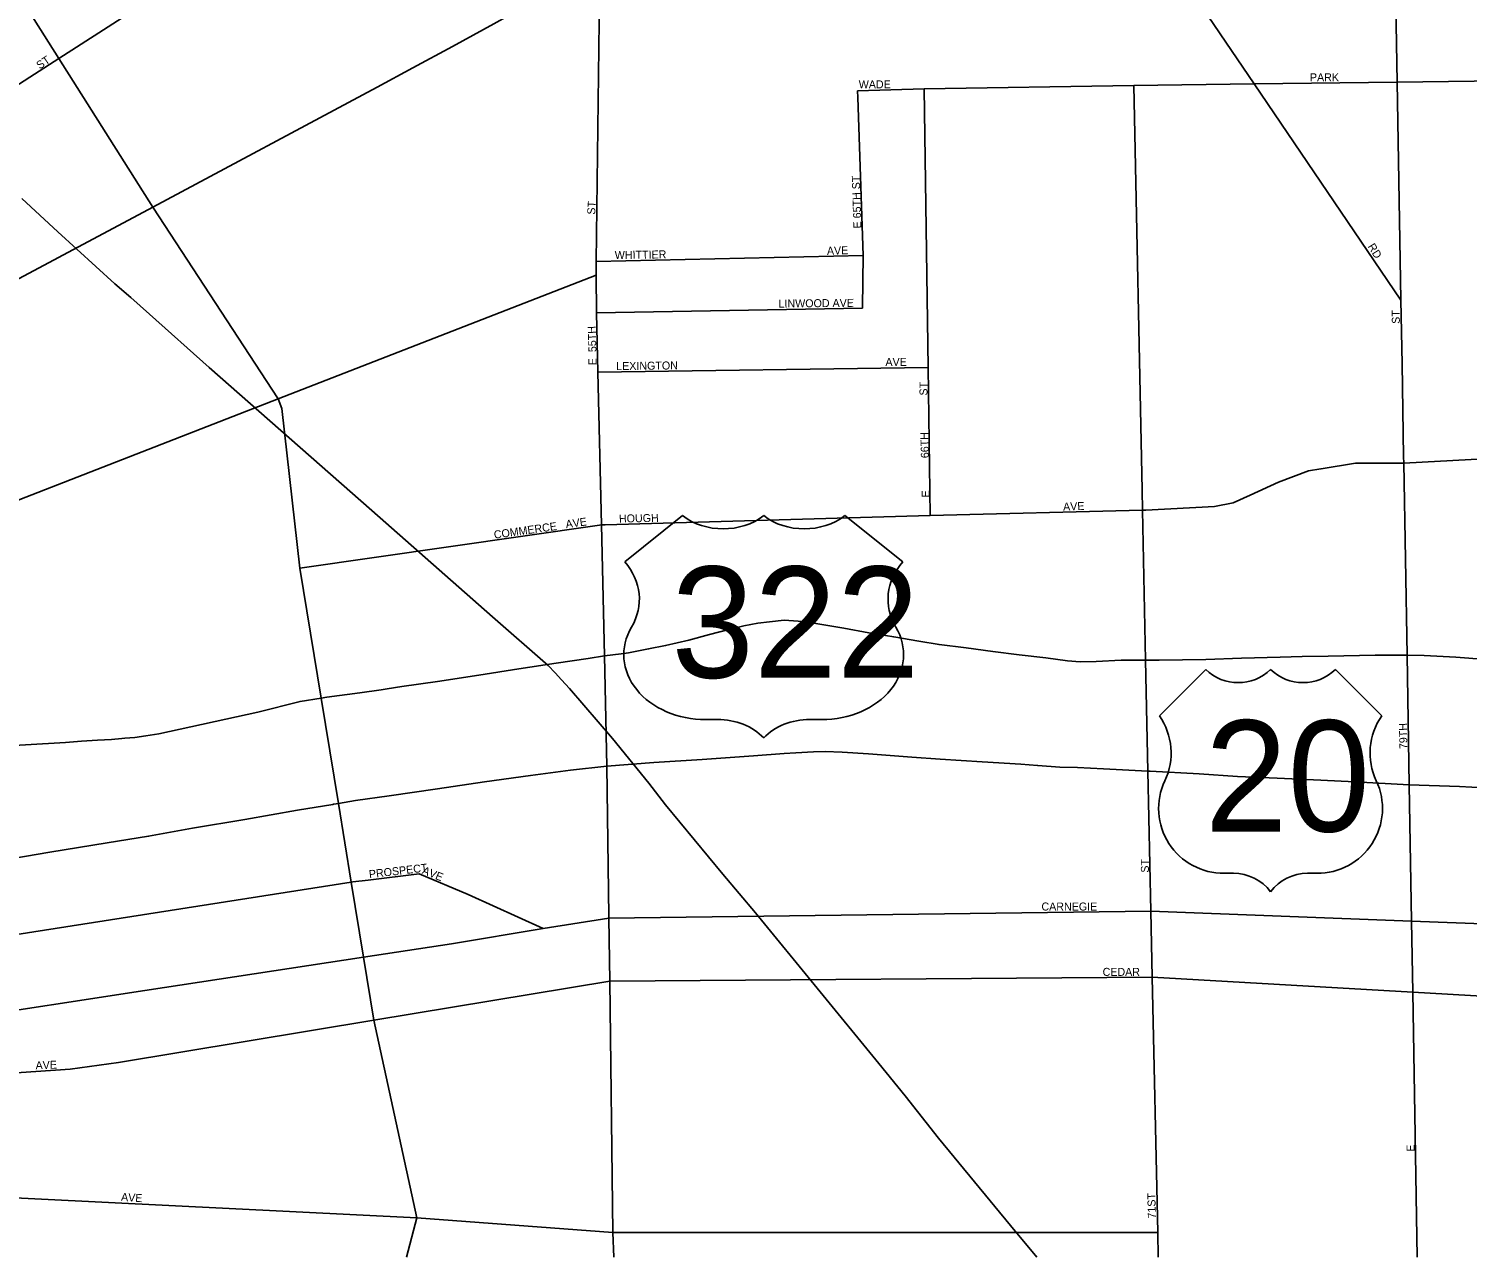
# Model space of a CAD drawing. Extents: x 2139079 to 2262683, y 1235796 to 1334992.
# Drawn here: x 2197328 to 2206334, y 1274636 to 1282328 of the extents above; entities that cross this region are included whole.
import ezdxf

# ---------------------------------------------------------------- set-up
doc = ezdxf.new("R2010")
doc.units = 0
for name, color, linetype in [('GM_X_City_Street', 7, 'Continuous'), ('GM_X_City_Street_Text', 7, 'Continuous'), ('GM_X_Rail_Line', 7, 'Continuous'), ('GM_X_US_Location', 7, 'Continuous'), ('GM_X_US_Route', 7, 'Continuous'), ('GM_X_US_Shield', 7, 'Continuous')]:
    doc.layers.add(name, color=color, linetype=linetype)

msp = doc.modelspace()

# ---------------------------------------------------------------- linework, layer by layer
at = {"layer": 'GM_X_City_Street'}
for points in [[(2205918.6, 1280628.8), (2205000.4, 1281982.7), (2204176.3, 1283197.8), (2202675.4, 1285411)], [(2195567.4, 1280882.4), (2195932.5, 1281121.6), (2196013.9, 1281174.9), (2197516.4, 1282140.7), (2200878.3, 1284302)], [(2199693.1, 1274636.1), (2199757.3, 1274882.4), (2199487.9, 1276121.4), (2199423.7, 1276514.9), (2199347, 1276984.3), (2199266.6, 1277477.3), (2199158.9, 1278137), (2199026, 1278950.7), (2198913.3, 1279950.5), (2198889.4, 1280010.3), (2198105.6, 1281211.1), (2197516.4, 1282140.7), (2197025, 1282915.9), (2196406.7, 1283843.3)], [(2200959.9, 1276772.6), (2200948.1, 1277711.7), (2200932.3, 1278401.1), (2200913.6, 1279220.8), (2200891.7, 1280176.8), (2200883.1, 1280549.8), (2200879.8, 1280784.3), (2200879.9, 1280871.4), (2200904.1, 1282710.1)], [(2205916.4, 1280755.8), (2205895, 1281994.1), (2205884.4, 1282599.7), (2205884.4, 1282599.7)], [(2202934.1, 1281951.1), (2204247.1, 1281973.2), (2205000.4, 1281982.7), (2205895, 1281994.1), (2209270.3, 1282037)], [(2202517.3, 1281938.9), (2202517.3, 1281938.9), (2202934.1, 1281951.1)], [(2202971.3, 1279279.3), (2202958.4, 1280207.2), (2202934.1, 1281951.1)], [(2204298.8, 1279439), (2204247.1, 1281973.2)], [(2202551.7, 1280907.9), (2202518.7, 1281897.1), (2202517.3, 1281938.9)], [(2200879.9, 1280871.4), (2202551.7, 1280907.9)], [(2202551.7, 1280907.9), (2202547.3, 1280584.6)], [(2192078.6, 1277394.3), (2192139, 1277429.1), (2192255.8, 1277493.6), (2192381.1, 1277540.8), (2193054.4, 1277782.2), (2193377.5, 1277898), (2194000, 1278121.1), (2195091.4, 1278534.1), (2195674.4, 1278761.3), (2196370.6, 1279030.8), (2198889.4, 1280010.3), (2200879.8, 1280784.3)], [(2205925.6, 1280228.9), (2205918.6, 1280628.8), (2205916.4, 1280755.8), (2205916.4, 1280755.8)], [(2202547.3, 1280584.6), (2202547.3, 1280584), (2202547.2, 1280578.6), (2200883.1, 1280549.8)], [(2200891.7, 1280176.8), (2202958.4, 1280207.2)], [(2205419.6, 1279573.1), (2205635, 1279607.5), (2205936.3, 1279607.8), (2207201.4, 1279677.6), (2207637.1, 1279689.3), (2207884.5, 1279701), (2208084.7, 1279759.8), (2208237.8, 1279806.9), (2208782.5, 1279945.6), (2209521.7, 1280141), (2209712.5, 1280189.9), (2209796.2, 1280201.6), (2209859.5, 1280204.6), (2209902.3, 1280201.9)], [(2205935.6, 1279649.4), (2205925.6, 1280228.9), (2205925.6, 1280228.9)], [(2206021.4, 1274636.1), (2205993.3, 1276295), (2205985.7, 1276739.7), (2205971.3, 1277594.8), (2205957.2, 1278406.4), (2205936.3, 1279607.8), (2205935.6, 1279649.4), (2205935.6, 1279649.4)], [(2204321.6, 1279314.5), (2204751.7, 1279336.9), (2204869.4, 1279360.5), (2204975.5, 1279407.5), (2205152.1, 1279489.9), (2205340.6, 1279560.5), (2205418.1, 1279572.8), (2205419.6, 1279573.1)], [(2204399.4, 1274636.1), (2204396, 1274790.1), (2204362.3, 1276390.1), (2204353.6, 1276802.7), (2204335.2, 1277679.2), (2204320.5, 1278374.7), (2204301.4, 1279313.5), (2204298.8, 1279439), (2204298.8, 1279439)], [(2200935.9, 1279221.4), (2202971.3, 1279279.3)], [(2202971.3, 1279279.3), (2204301.4, 1279313.5), (2204321.6, 1279314.5)], [(2199026, 1278950.7), (2200900.6, 1279220.4), (2200913.6, 1279220.8), (2200927.2, 1279221.2), (2200935.9, 1279221.4)], [(2194795.5, 1276268.4), (2194808.5, 1276270.4), (2195620.1, 1276396.8), (2195639.2, 1276399.7), (2195927.7, 1276444.6), (2196115.4, 1276475.2), (2196771, 1276582), (2199347, 1276984.3), (2199357.6, 1276985.9), (2199452, 1276997.4)], [(2199452, 1276997.4), (2199453, 1276997.5), (2199771.3, 1277036.1), (2200078.7, 1276907.4), (2200548.3, 1276694.8)], [(2195316.8, 1275884.2), (2195584.4, 1275925.4), (2195898.5, 1275973.8), (2196857.5, 1276121.5), (2198055.8, 1276306.1), (2199423.7, 1276514.9), (2199975.3, 1276599.1), (2200548.3, 1276694.8), (2200960.1, 1276758.7), (2204353.6, 1276802.7), (2205985.7, 1276739.7), (2208329.5, 1276653.5), (2208438.4, 1276656.1), (2209594.3, 1276683.5), (2210249.4, 1276698.5), (2211015.8, 1276660.8), (2211607.3, 1276645.7), (2211689.1, 1276641.1), (2211782.7, 1276635.3), (2211800.4, 1276631.3)], [(2200990.2, 1274636.1), (2200984.9, 1274790.2), (2200965.1, 1276364.1), (2200960.1, 1276758.7), (2200959.9, 1276772.6)], [(2195173.4, 1275563.7), (2195259.9, 1275543.1), (2195320.8, 1275531.8), (2195348.8, 1275529.9), (2195377.3, 1275531.8), (2196923.8, 1275769.9), (2197062.7, 1275778.9), (2197588.4, 1275813.1), (2197889.7, 1275856.3), (2199487.9, 1276121.4), (2200965.1, 1276364.1), (2204362.3, 1276390.1), (2205993.3, 1276295), (2208449.7, 1276154.3), (2211022.8, 1276017.2), (2211423.6, 1275997.3), (2211694.1, 1275984), (2211874.7, 1275974.6), (2211880.2, 1275974.3), (2212100, 1275965.1), (2212268.1, 1275954.8), (2212357.1, 1275951.5)], [(2197028.8, 1275019.3), (2197028.8, 1275019.3), (2199757.3, 1274882.4), (2200984.9, 1274790.2), (2203543.2, 1274790.2), (2203543.2, 1274790.2)], [(2203543.2, 1274790.2), (2203809.7, 1274790.2)], [(2203809.7, 1274790.2), (2203809.7, 1274790.2), (2204396, 1274790.1)]]:
    msp.add_lwpolyline(points, dxfattribs=at)
at = {"layer": 'GM_X_Rail_Line'}
msp.add_lwpolyline([(2197285.3, 1281264.1), (2197511.2, 1281056.8), (2197866.9, 1280730.2), (2197966.9, 1280645.2), (2198084, 1280540), (2198456.8, 1280207.4), (2199475.5, 1279311.8), (2200232.4, 1278646.6), (2200579.9, 1278340.1), (2200624.7, 1278295.3), (2200664.2, 1278252.1), (2200714.2, 1278196.9), (2200983.4, 1277883.7), (2201209.3, 1277604), (2201314.5, 1277469.1), (2201673.9, 1277033.6), (2201877.5, 1276793.4), (2202650.1, 1275848.6), (2202815.6, 1275645.8), (2203024.4, 1275381.8), (2203474.1, 1274835.1), (2203638.7, 1274636.1)], dxfattribs=at)
at = {"layer": 'GM_X_US_Route'}
for points in [[(2195310.7, 1279716.9), (2195406.6, 1279771.5), (2195540.9, 1279843.6), (2195772.2, 1279967.9), (2198105.6, 1281211.1), (2199508.9, 1281962.3), (2199732.1, 1282082.7), (2199981.1, 1282217.3), (2200240.2, 1282358.1), (2200816.9, 1282682.5), (2200904.1, 1282710.1)], [(2201037, 1278415), (2201083.2, 1278421.2), (2201209, 1278444.9), (2201314.9, 1278466.2), (2201460.6, 1278500.2), (2201590.3, 1278535.9), (2201710.1, 1278567.5), (2201803.9, 1278588.7), (2201891.8, 1278605.9), (2201965.7, 1278614.9), (2202057.7, 1278624.1), (2202145.9, 1278619.1), (2202256.2, 1278604.5), (2202430.8, 1278574.6), (2202587.3, 1278546.5), (2202743.8, 1278520.4), (2202900.4, 1278494.3), (2203026.8, 1278471.9), (2203197.2, 1278452), (2203363.7, 1278428), (2203528.1, 1278408), (2203694.6, 1278388.1), (2203831, 1278369.8), (2203911.1, 1278364.8), (2204011.2, 1278366), (2204167.3, 1278374), (2204320.5, 1278374.7), (2204405.6, 1278375), (2204697.9, 1278378.7), (2204920, 1278387.6), (2205162.2, 1278392.6), (2205300.3, 1278396.4), (2205462.5, 1278400.4), (2205756.7, 1278406.2), (2205957.2, 1278406.4), (2206065.1, 1278404), (2206263.4, 1278392.5), (2206449.8, 1278378.8)], [(2199572.9, 1278195.1), (2199664.3, 1278208.7), (2199886.2, 1278241.6), (2200146, 1278281), (2200395.7, 1278320.2), (2200629.6, 1278355.3), (2200830.3, 1278385.7), (2200932.3, 1278401.1)], [(2200932.3, 1278401.1), (2201037, 1278415)], [(2197911.4, 1277883.8), (2197930.5, 1277885.6), (2197992.9, 1277890.4), (2198061.7, 1277900), (2198141.8, 1277912.8), (2198762.9, 1278048.9), (2199026.8, 1278116.4), (2199158.9, 1278137), (2199194.7, 1278142.6), (2199400.5, 1278169.3), (2199535, 1278189.4), (2199572.9, 1278195.1)], [(2196216.8, 1277747.9), (2196386.8, 1277773.9), (2196591.7, 1277805.3), (2196875.6, 1277820), (2197559.1, 1277860), (2197658.4, 1277866.4), (2197757.6, 1277874.4), (2197845.6, 1277877.6), (2197911.4, 1277883.8)], [(2199237.4, 1277472.4), (2199266.6, 1277477.3), (2199373.1, 1277495.2), (2199584.9, 1277525.9), (2199886.7, 1277569.9), (2200180.5, 1277613.7), (2200468.3, 1277651.4), (2200720.2, 1277686.7), (2200948.1, 1277711.7), (2201242.2, 1277733.4), (2201544.3, 1277753.3), (2201866.3, 1277775.4), (2202056.5, 1277789.3), (2202057.8, 1277789.4)], [(2202057.8, 1277789.4), (2202130.4, 1277794.8), (2202240.4, 1277800.2), (2202314.5, 1277803.1), (2202420.7, 1277798.5), (2202585, 1277788.5), (2202857.6, 1277767.9), (2203033.9, 1277754.1), (2203296.4, 1277737.3), (2203538.9, 1277722.4), (2203643.7, 1277715.1)], [(2203643.7, 1277715.1), (2203645.2, 1277715), (2203783.4, 1277705.4), (2203893.6, 1277702.8), (2204055.8, 1277694.8), (2204335.2, 1277679.2), (2204348.4, 1277678.5), (2204654.9, 1277662.3), (2204895.4, 1277645.3), (2205143.8, 1277636.4), (2205416.3, 1277623.8), (2205630.7, 1277612.5), (2205971.3, 1277594.8)], [(2205971.3, 1277594.8), (2206285.8, 1277582.7), (2206594.3, 1277566.5), (2206870.8, 1277554), (2207105.2, 1277542.9), (2207417.7, 1277530.8), (2207720.3, 1277516.6), (2208048.8, 1277502.7), (2208328.4, 1277492), (2208419.5, 1277497.5), (2208650.6, 1277511.6), (2209013.3, 1277524.3), (2209295.9, 1277536.5), (2209590.5, 1277548.8), (2209899.1, 1277561.1), (2210251.7, 1277573.8), (2210544.3, 1277588), (2210889, 1277600.7), (2210987.9, 1277605.5), (2210990.1, 1277605.6)], [(2195969.9, 1276936), (2196047.8, 1276947.6), (2196707.8, 1277046.4), (2197067.5, 1277105.1), (2197459.1, 1277172.2), (2197818.7, 1277230.9), (2198078.5, 1277272.2), (2198354.2, 1277321.9), (2198679.9, 1277376.1), (2199011.5, 1277434.5), (2199231.3, 1277471.3), (2199236.5, 1277472.2), (2199237.4, 1277472.4)]]:
    msp.add_lwpolyline(points, dxfattribs=at)
at = {"layer": 'GM_X_US_Shield'}
for p, q in [((2201421.7, 1279279.6), (2201059.2, 1278989.5)), ((2202799.4, 1278989.5), (2202436.8, 1279279.6)), ((2204696.5, 1278316.6), (2204406.5, 1278026.5)), ((2205798.7, 1278026.5), (2205508.6, 1278316.6)), ((2201566.7, 1278003.4), (2201639.2, 1278003.4)), ((2202219.3, 1278003.4), (2202291.8, 1278003.4)), ((2204812.5, 1277040.4), (2204870.5, 1277040.4)), ((2205334.6, 1277040.4), (2205392.6, 1277040.4))]:
    msp.add_line(p, q, dxfattribs=at)
for centre, radius, start, end in [((2204899.5, 1278523.7), 290, 225.573, 314.427), ((2205305.6, 1278523.7), 290, 225.573, 314.427), ((2204073.9, 1277793.6), 406.1, 334.54712, 35.00093), ((2206131.3, 1277793.6), 406.1, 144.99907, 205.45288), ((2204808, 1277446.4), 406.1, 154.83192, 270.63826), ((2205397.1, 1277446.4), 406.1, 269.36174, 25.16808), ((2204870.5, 1276750.3), 290, 36.8699, 90), ((2205334.6, 1276750.3), 290, 90, 143.1301)]:
    msp.add_arc(centre, radius, start, end, dxfattribs=at)
for centre, major_axis, start_param, end_param in [((2201675.5, 1279486.7), (-362.5, 0), 0.795399, 2.346194), ((2202183.1, 1279486.7), (-362.5, 0), 0.795399, 2.346194), ((2200643.4, 1278756.6), (507.6, 0), 5.838949, 6.894067), ((2203215.2, 1278756.6), (-507.6, 0), 5.672304, 6.727422), ((2201561.1, 1278409.4), (507.6, 0), 2.702327, 4.723529), ((2202297.5, 1278409.4), (-507.6, 0), 1.559657, 3.580859), ((2201639.2, 1277713.4), (-362.5, 0), 3.785094, 4.712389), ((2202219.3, 1277713.4), (-362.5, 0), 4.712389, 5.639684)]:
    msp.add_ellipse(centre, major_axis=major_axis, ratio=0.8, start_param=start_param, end_param=end_param, dxfattribs=at)

# ---------------------------------------------------------------- texts
at = {"layer": 'GM_X_City_Street_Text'}
for s, rotation, p in [('ST', 34.70215, (2197397.2, 1282072)), ('PARK', 0.00001, (2205349, 1281998.9)), ('WADE', 0.00001, (2202524.2, 1281954.9)), ('E 65TH ST', 91.78896, (2202541.2, 1281078.4)), ('ST', 86.42535, (2200873.6, 1281162.9)), ('AVE', 1.9739, (2202325.9, 1280912.1)), ('RD', 302.01276, (2205708.9, 1280964.9)), ('WHITTIER', 0.85787, (2200997.2, 1280885.7)), ('LINWOOD AVE', 0.58654, (2202022.5, 1280582.1)), ('ST', 90, (2205911.6, 1280480.3)), ('55TH', 91.78907, (2200882.4, 1280304)), ('E', 90, (2200882.4, 1280220.7)), ('LEXINGTON', 0.71578, (2201006.1, 1280190.5)), ('AVE', 0.00001, (2202691.4, 1280216.9)), ('ST', 90, (2202954.8, 1280031.5)), ('66TH', 91.3632, (2202963.6, 1279639.7)), ('E', 90, (2202968, 1279393.5)), ('AVE', 1.9739, (2203804.3, 1279310.5)), ('AVE', 7.85561, (2200692.5, 1279200.4)), ('HOUGH', 1.14952, (2201023.6, 1279235.7)), ('COMMERCE', 8.02847, (2200243.7, 1279134.4)), ('79TH', 91.3632, (2205960, 1277818.1)), ('PROSPECT', 6.61296, (2199460.7, 1277009.2)), ('ST', 90, (2204340.8, 1277043.9)), ('AVE', 337.83108, (2199786.5, 1277039.4)), ('CARNEGIE', 0.00001, (2203668.2, 1276806.9)), ('CEDAR', 0.00001, (2204051, 1276397.7)), ('AVE', 1.9739, (2197371.5, 1275812.5)), ('E', 90, (2206004, 1275297.1)), ('AVE', 356.05688, (2197904.8, 1274989.7)), ('71ST', 91.43675, (2204384.8, 1274878.8))]:
    msp.add_text(s, height=50, rotation=rotation, dxfattribs=at).set_placement(p)
at = {"layer": 'GM_X_US_Location'}
for s, p in [('/', (2201929.8, 1278612)), ('0', (2201929.8, 1278612)), ('/', (2205102.2, 1277644)), ('0', (2205102.2, 1277644))]:
    msp.add_text(s, height=1, dxfattribs=at).set_placement(p)
for s, p in [('322', (2201622.2, 1278405)), ('20', (2204895.8, 1277437))]:
    msp.add_text(s, height=1, rotation=0.00001, dxfattribs=at).set_placement(p)
at = {"layer": 'GM_X_US_Shield'}
for s, p in [('322', (2201351, 1278264.4)), ('20', (2204691, 1277301.4))]:
    msp.add_text(s, height=696.1, dxfattribs=at).set_placement(p)

doc.saveas('drawing.dxf')
